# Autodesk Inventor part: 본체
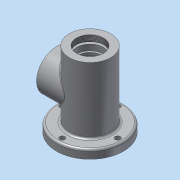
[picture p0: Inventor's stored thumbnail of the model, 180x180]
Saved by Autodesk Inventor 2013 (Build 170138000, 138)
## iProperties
Created: 2016-08
Part Number: 본체
Material: 알루미늄 6061
Document SubType Name: Modeling
Designer: dgall
Density: 2.71 g/cm^3
Mass: 771.031 g
Surface Area: 632.581 cm^2
Volume: 284.513 cm^3
Author: dgall
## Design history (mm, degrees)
sketch "스케치1"
  geometry: C1 r 31 at (0, 0); 1 further point
  constraints: 1 centre point, 1 coincident
  dimensions: "d0" = 62 diameter of C1
extrude "돌출1" new body sketch "스케치1" distance "d2" = 115; taper "d3" = 0 deg
node "작업 평면1"
sketch "스케치2"
  geometry: C1 r 50 at (0, 0); 1 further point
  constraints: 1 centre point, 1 coincident
  dimensions: "d5" = 100 diameter of C1
extrude "돌출2" join sketch "스케치2" distance "d7" = 13; taper "d8" = 0 deg
node "작업 평면2"
sketch "스케치4" dims "d14" = 83
  geometry: L1 (0, 0)-(0, 41.5); C1 r 31 at (0, 0) reference; C2 r 4 at (0, 41.5)
  constraints: 2 coincident, 2 end point, 1 centre point, 1 vertical, 1 vertical alignment, 2 other
  dimensions: "d16" = 8 diameter of C2
extrude "돌출4" cut sketch "스케치4" stored distance "d17" = 13; taper "d18" = 0 deg
fillet "모깎기1" dims "d22" = 3
sketch "스케치5"
  geometry: C1 r 31 at (0, 0) reference
hole "구멍1" sketch "스케치5" at (0, 0) diameter "d23" = 40.376; stored, may be unused: countersink angle "d27" = 90 deg, drill point angle "d29" = 0 deg; dims "d24" = 6, "d25" = 4, "d26" = 2, "d28" = 9
sketch "스케치6"
  geometry: C1 r 20.188 at (0, 0) reference; C2 r 24 at (0, 0)
  constraints: 1 centre point, 1 coincident
  dimensions: "d30" = 48 diameter of C2
extrude "돌출5" cut sketch "스케치6" distance "d32" = 3; taper "d33" = 0 deg
sketch "스케치7"
  geometry: C1 r 24 at (0, 0) reference; C2 r 20 at (0, 0)
  constraints: 1 centre point, 1 coincident
  dimensions: "d34" = 40 diameter of C2
extrude "돌출6" cut sketch "스케치7" distance "d36" = 9; taper "d37" = 0 deg
fillet "모깎기2" dims "d50" = 3
sketch "스케치9"
  geometry: C1 r 20 at (0, 0) reference; C2 r 17.5 at (0, 0)
  constraints: 1 centre point, 1 coincident
  dimensions: "d52" = 35 diameter of C2
extrude "돌출7" cut sketch "스케치9" distance "d54" = 3.75; taper "d55" = 0 deg
sketch "스케치10"
  geometry: C1 r 17.5 at (0, 0) reference; C2 r 18.5 at (0, 0)
  constraints: 1 centre point, 1 coincident
  dimensions: "d56" = 37 diameter of C2
extrude "돌출8" cut sketch "스케치10" distance "d58" = 1.75; taper "d59" = 0 deg
sketch "스케치11"
  geometry: C1 r 18.5 at (0, 0) reference; C2 r 17.5 at (0, 0)
  constraints: 1 centre point, 1 coincident
  dimensions: "d60" = 35 diameter of C2
extrude "돌출9" cut sketch "스케치11" distance "d62" = 11; taper "d63" = 0 deg
chamfer "모따기1" distance "d64" = 1; stored, may be unused: second distance "d65" = 2, angle "d66" = 45 deg
sketch "스케치12"
  geometry: C1 r 16.5 at (0, 0) reference; C2 r 26 at (0, 0)
  constraints: 1 centre point, 1 coincident
  dimensions: "d67" = 52 diameter of C2
extrude "돌출10" cut sketch "스케치12" distance "d69" = 38; taper "d70" = 0 deg
sketch "스케치13"
  geometry: C1 r 26 at (0, 0) reference; C2 r 17.5 at (0, 0)
  constraints: 1 centre point, 1 coincident
  dimensions: "d71" = 35 diameter of C2
extrude "돌출11" cut sketch "스케치13" distance "d73" = 11; taper "d74" = 0 deg
chamfer "모따기2" distance "d75" = 1; stored, may be unused: second distance "d76" = 2, angle "d77" = 45 deg
sketch "스케치14"
  geometry: C1 r 17.5 at (0, 0) reference; C2 r 16.5 at (0, 0)
  constraints: 1 centre point, 1 coincident
  dimensions: "d78" = 33 diameter of C2
extrude "돌출12" cut sketch "스케치14" distance "d80" = 5; taper "d81" = 0 deg
fillet "모깎기4" dims "d82" = 3
sketch "스케치15"
  geometry: C1 r 13.5 at (0, 0) reference; C2 r 10 at (0, 0)
  constraints: 1 centre point, 1 coincident
  dimensions: "d83" = 20 diameter of C2
sketch "스케치18"
  geometry: L1 (0, 0)-(0, 37.8); L2 (21, 0)-(16, 14); L3 (16, 14)-(0, 14); L4 (-31, 0)-(31, 0) reference; L5 (21, 0)-(0, 0)
  constraints: 8 end point, 1 perpendicular, 1 point on line, 1 vertical
  dimensions: "d101" = 42 diameter of L2.start L1; "d103" = 32 diameter of L2.end L1; "d104" = 14 vertical distance of L2.start L2.end; "d105" = 0 distance from line of L4 L2.start
revolve "회전1" sketch "스케치18" stored, may be unused: angle "d106" = 90 deg
fillet "모깎기5" dims "d107" = 3
extrude "돌출16" cut sketch "스케치15" distance "d108" = 2.7; taper "d109" = 0 deg
sketch "스케치19"
  geometry: C1 r 10 at (0, 0) reference; C2 r 12.5 at (0, 0)
  constraints: 1 centre point, 1 coincident
  dimensions: "d110" = 25 diameter of C2
extrude "돌출17" cut sketch "스케치19" stored distance "d112" = 2.7; taper "d113" = 0 deg
chamfer "모따기5" distance "d114" = 0.7; stored, may be unused: second distance "d115" = 2, angle "d116" = 30 deg
node "작업 평면3"
node "작업 평면4"
node "작업 평면5"
node "작업 평면6"
sketch "스케치23"
  geometry: L1 (31, 115)-(-31, 115) reference; L2 (0, 115)-(0, 59); C1 r 30 at (0, 59); 1 further point
  constraints: 2 end point, 1 centre point, 1 coincident, 1 midpoint, 1 perpendicular
  dimensions: "d123" = 56 distance of L2.start L2.end; "d125" = 60 diameter of C1
extrude "돌출18" join sketch "스케치23" stored distance "d126" = 2.7; taper "d127" = 0 deg
sketch "스케치24"
  geometry: C1 r 30 at (0, 0) reference; C2 r 19 at (0, 0); 1 further point
  constraints: 1 centre point, 1 coincident
  dimensions: "d128" = 38 diameter of C2
extrude "돌출19" cut sketch "스케치24" stored distance "d130" = 2.7; taper "d131" = 0 deg
sketch "스케치25" dims "d132" = 48
  geometry: L1 (0, 0)-(0, 24); C1 r 30 at (0, 0) reference; 1 further point
  constraints: 2 end point, 1 coincident, 1 vertical, 1 vertical alignment, 2 other
hole "구멍3" sketch "스케치25" at (0, 24) diameter "d134" = 3.242; stored, may be unused: countersink angle "d138" = 90 deg, drill point angle "d140" = 118 deg; dims "d135" = 8, "d136" = 4, "d137" = 2, "d139" = 10
chamfer "모따기6" distance "d144" = 1; stored, may be unused: second distance "d145" = 2, angle "d146" = 30 deg
node "작업 평면7"
sketch "스케치26"
  geometry: L1 (43.002, 79.739)-(43.002, 38.261); L2 (43.002, 38.261)-(36.998, 38.261); L3 (36.998, 38.261)-(36.998, 79.739); L4 (36.998, 79.739)-(43.002, 79.739); L5 (40, 79.739)-(40, 38.261); L6 (43.002, 59)-(36.998, 59); L7 (31, 115)-(-31, 115) reference; L8 (50, 89)-(50, 29) reference; 1 further point
  constraints: 4 end point, 4 midpoint, 2 other
  dimensions: "d148" = 56 distance from line of L6.start L7; "d149" = 10 distance from line of L5.end L8
feature "엠보싱2" sketch "스케치26" dims "d150" = 0.5, "d151" = 0
fillet "모깎기6" dims "d152" = 3
node "솔리드1"
pattern_circular "원형 패턴1" dims angle "d20" = 360 deg
pattern_circular "원형 패턴3" dims angle "d142" = 360 deg
other parameters: "d4" = 3, "d117" = 44.75, "d147" = 37
